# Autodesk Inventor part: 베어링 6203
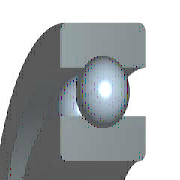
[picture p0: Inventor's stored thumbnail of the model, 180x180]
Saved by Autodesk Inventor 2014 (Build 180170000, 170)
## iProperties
IsCustomPart: 0
Company: 한국ATC센터
Created: 2015-11
Part Number: 베어링 6203
Material: 강철, 연강
Description: 깊은 그루브 볼 베어링
Document SubType Name: Modeling
Standard: KS B 2023
Designer: mdu
Standards Organization: KS
Language: ko-KR
Size Designation: 6203 - 17 x 40 x 12
Categories: <MemberInstance><Categories><Category DisplayName="샤프트 부품" InternalName="7f7aeb1f-a693-4053-b835-cee3144e0d98" Mnemonic="SHFT"><Category DisplayName="베어링" Inter
Density: 7.86 g/cm^3
Appearance: 노란색
Mass: 58.8203 g
Surface Area: 64.3582 cm^2
Volume: 7.4835 cm^3
Author: mdu
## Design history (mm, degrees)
sketch "스케치" dims "d0" = 5.98 (= -0.26 x WD + 0.26 x BD)
  geometry: L1 (3.01, 14.25)-(8.99, 14.25); L2 (6, 14.25)-(6, 11.26); L3 (6, 14.25)-(6, 17.24); L4 (3.778, 12.249)-(0, 12.249); L5 (0, 8.5)-(12, 8.5); L6 (3.778, 16.251)-(0, 16.251); L7 (0, 20)-(12, 20); L8 (12, 8.5)-(12, 12.249); L9 (8.222, 12.249)-(12, 12.249); L10 (8.222, 16.251)-(12, 16.251); L11 (12, 20)-(12, 16.251); L12 (-1.4, 0)-(8.4, 0) reference; L13 (0, -0.3)-(0, 5.3) reference
  constraints: 22 end point, 4 point on line, 2 collinear, 2 perpendicular, 2 symmetric about line, 1 midpoint, 1 parallel, 14 other
  dimensions: "d9" = 17 diameter of L5 L12 (= WD); "d11" = 40 diameter of L7 L12 (= BD); "d12" = 12 distance between parallel lines of L8 L13 (= KB); "d13" = 24.498 diameter of L9 L12 (= 0.326 x BD + 0.674 x WD)
revolve "본체" stored, may be unused: angle "d6" = 90 deg
revolve "볼" stored, may be unused: angle "d7" = 90 deg
pattern_circular "IDS_ARRAYBALL[SIMPL:T]" dims angle "d3" = 360 deg
body "Solid1"
fillet "모깎기1" dims "d1" = 0.6 (= KRS)
other parameters: "WD" = 17 [user parameter; used in 5 equation terms], "BD" = 40 [user parameter; used in 5 equation terms], "KB" = 12 [user parameter; used in 1 equation term], "KRS" = 0.6 [user parameter; used in 1 equation term], "d4" = 0, "d5" = 0, "d8" = 0, "d14" = 0, "d15" = 0, "BBA" = 0 [user parameter], "BC0" = 4750000 [user parameter], "BC" = 9560000 [user parameter], "WR" = 8.5 (= 0.5 x WD) [user parameter]
